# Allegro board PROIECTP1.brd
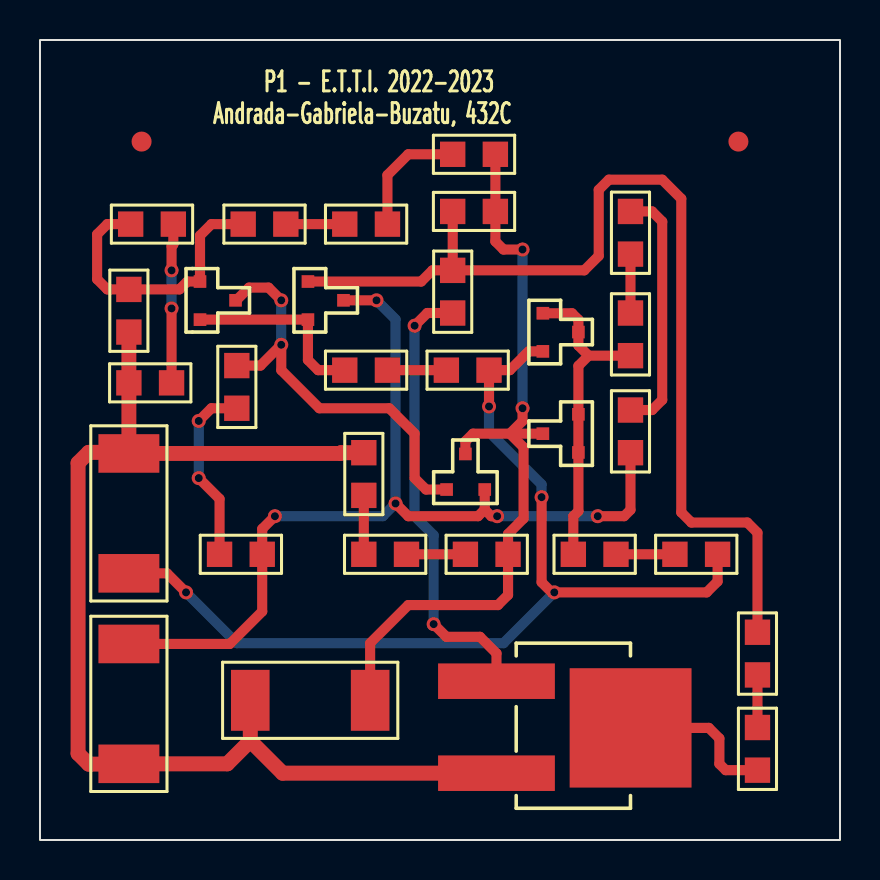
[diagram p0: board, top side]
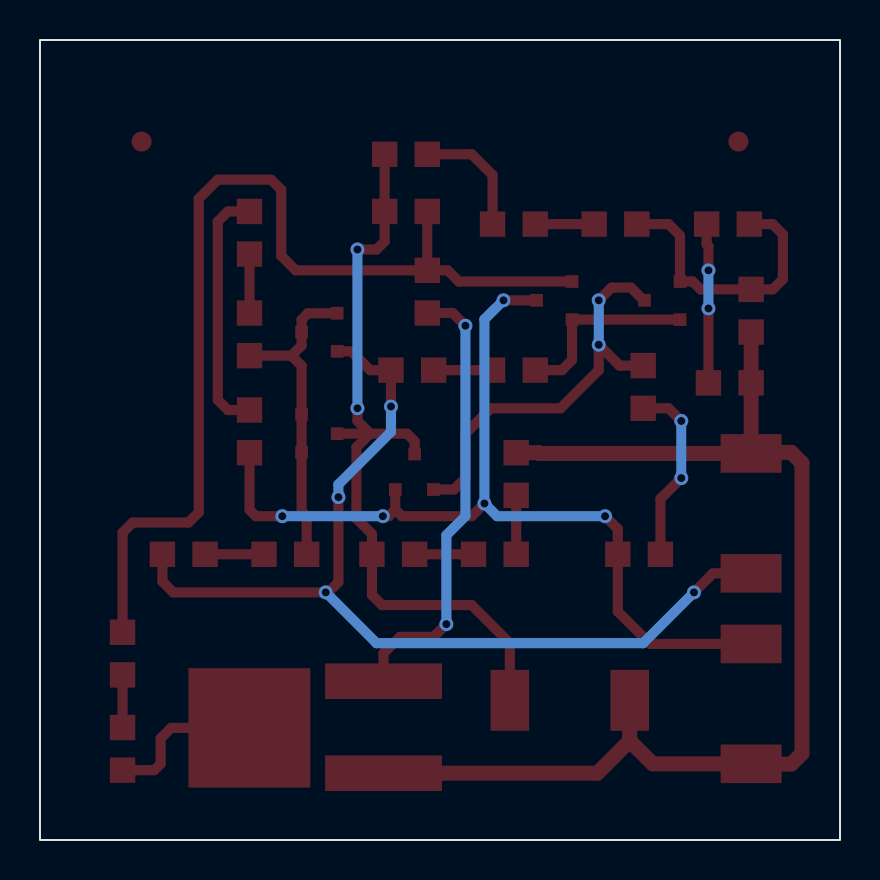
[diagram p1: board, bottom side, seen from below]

Outline 40.01 x 40.01 mm; copper layers: TOP, BOTTOM. Coordinates in mm from the lower left corner of the outline.
Outline path: rectangle 0,0 40.01,40.01

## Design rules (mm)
nets with their own width: min track width 0.508; nets N07562 N07566 N07674 N07678 N07682 N07786 N07830 N07834 N07854 N07900 N08156 N08192 N08330 N08354 N077021 N077181 N078461 N079281 N079441 N080220 N082081
nets with their own width: min track width 0.749; nets GND

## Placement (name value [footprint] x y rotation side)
C1  1n  [SMC0805]  4.45 25.4 90 top
C2  1n  [SMC0805]  20.64 34.29 0 top
J1  CON2  [SMR2512]  4.45 13.34 90 top
J2  CON2  [SMR2512]  4.45 3.81 90 top
J3  CON2  [SMR2512]  16.51 6.99 180 top
NOREF  Value  [unnamed]  34.92 34.92 0 top
NOREF#2  Value  [unnamed]  5.08 34.92 0 top
NOREF#3  -  [#2]  0 40.01 0 top
NOREF#4  -  [#2]  0 0 90 top
Q1  BC856B  [SOT23]  14.29 26.99 0 top
Q2  BC856B  [SOT23]  8.89 26.99 0 top
Q3  BC856B  [SOT23]  26.04 25.4 0 top
Q4  BC856B  [SOT23]  26.04 20.32 180 top
Q5  BC846B  [SOT23]  21.27 18.41 90 top
Q7  IRFR120  [TO252AA]  22.86 7.94 270 top
R1  8.2k  [SMR0805]  4.45 22.86 0 top
R2  220  [SMR0805]  6.67 30.8 180 top
R3  8.2k  [SMR0805]  10.16 30.8 0 top
R4  220  [SMR0805]  15.24 30.8 0 top
R5  910  [SMR0805]  21.27 14.29 0 top
R6  10  [SMR0805]  16.19 14.29 0 top
R7  33  [SMR0805]  16.19 19.37 270 top
R8  330  [SMR0805]  15.24 23.5 0 top
R9  68  [SMR0805]  20.32 23.5 0 top
R10  150  [SMR0805]  9.84 21.59 90 top
R11  10  [SMR0805]  11.11 14.29 180 top
R12  220  [SMR0805]  29.53 26.35 270 top
R13  68  [SMR0805]  29.53 31.43 270 top
R14  4.7  [SMR0805]  29.53 19.37 90 top
R15  150  [SMR0805]  26.67 14.29 0 top
R16  150  [SMR0805]  31.75 14.29 0 top
R17  10k  [SMR0805]  20.64 31.43 0 top
R18  100k  [SMR0805]  20.64 26.35 90 top
R19  15k  [SMR0805]  35.88 8.26 90 top
R20  510  [SMR0805]  35.88 3.49 90 top

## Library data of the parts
C1 C2 = C
J1-J3 = CON2
Q1-Q4 = BC856B
Q5 = BC846B
Q7 = IRFR120
R1-R20 = R

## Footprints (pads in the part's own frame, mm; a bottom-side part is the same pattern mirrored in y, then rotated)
SMC0805
  rect 1.27x1.27 smd: 1(0,0) 2(2.134,0)
SMR0805
  rect 1.27x1.27 smd: 1(0,0) 2(2.134,0)
SMR2512
  rect 1.93x3.048 smd: 1(0,0) 2(5.994,0)
SOT23
  rect 0.635x0.635 smd: 1(-0.889,0.94) 2(-0.889,-0.965) 3(0.889,0)
TO252AA
  rect 1.778x5.842 smd: 1(-0.004,-0.034) 3(4.596,-0.034)
  rect 5.969x6.096 smd: 2(2.332,6.673)
unnamed
  round 1 smd: 1(0,0)

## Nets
GND: C1.1 J1.2 J2.1 J3.2 Q7.3(S) R1.1 R7.1
N07562: R1.2 R2.1
N07566: C1.2 Q2.1(B) R2.2 R3.1
N07674: R3.2 R4.1
N07678: C2.1 R4.2
N07682: C2.2 J3.1 Q4.3(C) Q5.3(C) R5.2 R17.2
N07786: Q1.2(E) Q2.2(E) R8.1
N07830: J1.1 Q3.2(E) R9.2 R16.2
N07834: Q2.3(C) Q5.1(B) R10.2
N07854: J2.2 Q1.3(C) Q5.2(E) R11.1 R14.1
N07900: Q3.1(B) Q3.3(C) Q4.1(B) Q4.2(E) R12.2 R15.1
N08156: Q1.1(B) R17.1 R18.2 R19.2
N08192: Q7.1(G) R18.1
N08330: R8.2 R9.1
N08354: R19.1 R20.2
N077021: R5.1 R6.2
N077181: R6.1 R7.2
N078461: R10.1 R11.2
N079281: R12.1 R13.2
N079441: R13.1 R14.2
N080220: R15.2 R16.1
N082081: Q7.2(D) R20.1

Pads without a net: NOREF 1; NOREF#2 1

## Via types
v1: diameter 0.7, hole 0.4, TOP to BOTTOM, 19 vias

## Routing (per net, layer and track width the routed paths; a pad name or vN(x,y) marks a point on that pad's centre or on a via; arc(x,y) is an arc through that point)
GND: length 59.5
  TOP w0.749: 10.52,6.99 10.52,4.96 ; 10.52,4.96 12.13,3.34 Q7.3 ; 10.52,4.96 9.37,3.81 J2.1 4.43,3.79 2.44,3.79 1.91,4.32 1.91,18.85 2.44,19.38 4.39,19.38 J1.2 ; R7.1 15.06,19.37 15.02,19.33 J1.2 ; J1.2 R1.1 C1.1
N07562: length 8
  TOP w0.508: R2.1 6.67,29.78 6.58,29.69 v1(6.58,28.49) ; R1.2 v1(6.58,26.58)
  BOTTOM w0.508: v1(6.58,26.58) v1(6.58,28.49)
N07566: length 14.3
  TOP w0.508: R2.2 3.37,30.8 2.86,30.29 2.86,28.04 3.37,27.53 C1.2 6.97,27.53 7.37,27.93 8,27.93 8,30.23 8.57,30.8 R3.1
N07674: length 2.9
  TOP w0.508: R3.2 R4.1
N07678: length 6.1
  TOP w0.508: C2.1 18.41,34.29 17.37,33.25 R4.2
N07682: length 39.4
  TOP w0.508: 23.5,20.32 24.13,20.95 v1(24.13,21.59) ; 23.5,20.32 24.18,19.63 24.18,16.08 23.41,15.3 R5.2 23.41,12.26 22.9,11.75 18.41,11.75 16.51,9.84 J3.1 ; 23.5,20.32 21.65,20.32 21.27,19.94 Q5.3 ; 23.5,20.32 Q4.3 ; C2.2 R17.2 22.77,29.93 23.18,29.53 v1(24.13,29.53)
  BOTTOM w0.508: v1(24.13,29.53) v1(24.13,21.59)
N07786: length 9.5
  TOP w0.508: R8.1 13.91,23.5 13.4,24 Q1.2 8,26.02
N07830: length 49.1
  TOP w0.508: R16.2 33.88,12.93 33.34,12.38 v1(25.72,12.38) 25.59,12.38 25.08,12.89 v1(25.08,17.14) ; Q3.2 24.43,24.43 23.5,23.5 R9.2 v1(22.45,21.68) ; v1(7.3,12.38) 6.35,13.34 J1.1
  BOTTOM w0.508: v1(22.45,21.68) 22.45,20.41 25.08,17.78 v1(25.08,17.14) ; v1(25.72,12.38) 23.18,9.84 9.84,9.84 v1(7.3,12.38)
N07834: length 21
  TOP w0.508: v1(12.06,26.99) 11.43,27.62 10.45,27.62 9.82,26.99 Q2.3 ; Q5.1 19.3,17.53 18.73,18.1 18.73,20.32 17.46,21.59 13.97,21.59 12.06,23.5 v1(12.06,24.77) 11.02,23.72 R10.2
  BOTTOM w0.508: v1(12.06,24.77) v1(12.06,26.99)
N07854: length 47.1
  TOP w0.508: v1(27.89,16.19) 29.21,16.19 29.53,16.51 R14.1 ; Q1.3 v1(16.83,26.99) ; v1(22.86,16.19) 22.57,16.19 22.24,16.52 ; v1(17.78,16.83) 18.41,16.19 21.91,16.19 22.24,16.52 ; 22.24,16.52 Q5.2 ; J2.2 9.49,9.8 11.11,11.43 R11.1 11.11,15.56 v1(11.75,16.19)
  BOTTOM w0.508: v1(11.75,16.19) 17.14,16.19 v1(17.78,16.83) 17.78,26.04 v1(16.83,26.99) ; v1(27.89,16.19) v1(22.86,16.19)
N07900: length 16.3
  TOP w0.508: Q3.1 26.6,26.34 26.92,26.02 Q3.3 26.92,24.73 27.43,24.22 ; 27.43,24.22 R12.2 ; 27.43,24.22 26.92,23.71 Q4.2 Q4.1 26.92,16.45 26.67,16.19 R15.1
N08156: length 50.9
  TOP w0.508: R19.2 35.88,15.37 35.37,15.88 32.58,15.88 32.07,16.38 32.07,32.07 31.11,33.02 28.45,33.02 27.94,32.51 27.94,29.21 27.22,28.49 R18.2 ; R18.2 19.62,28.49 19.06,27.93 Q1.1 ; R18.2 R17.1
N08192: length 22.6
  TOP w0.508: Q7.1 22.83,9.33 22,10.16 20.32,10.16 v1(19.68,10.79) ; v1(18.73,25.72) 19.37,26.35 R18.1
  BOTTOM w0.508: v1(18.73,25.72) 18.73,16.19 19.68,15.24 v1(19.68,10.79)
N08330: length 2.9
  TOP w0.508: R8.2 R9.1
N08354: length 2.6
  TOP w0.508: R19.1 R20.2
N077021: length 2.9
  TOP w0.508: R6.2 R5.1
N077181: length 2.9
  TOP w0.508: R7.2 R6.1
N078461: length 9.3
  TOP w0.508: R10.1 8.57,21.59 v1(7.94,20.95) ; R11.2 8.98,17.06 v1(7.94,18.1)
  BOTTOM w0.508: v1(7.94,20.95) v1(7.94,18.1)
N079281: length 2.9
  TOP w0.508: R12.1 R13.2
N079441: length 12.5
  TOP w0.508: R14.2 30.61,21.5 31.11,22.01 31.11,30.92 30.61,31.43 R13.1
N080220: length 2.9
  TOP w0.508: R16.1 R15.2
N082081: length 8
  TOP w0.508: Q7.2 33.45,5.61 33.97,5.08 33.97,3.81 34.29,3.49 R20.1

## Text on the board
Ref Des/Silkscreen Top: Andrada-Gabriela-Buzatu, 432C | P1 - E.T.T.I. 2022-2023
XSECTION_CHART: *  SURFACE - AIR 0 MIL | L1: TOP CONDUCTOR - COPPER 0.8 MIL | *  DIELECTRIC - FR-4 59 MIL | L2: BOTTOM CONDUCTOR - COPPER 0.8 MIL | DESIGN CROSS SECTION CHART | ___________________________ | TOTAL THICKNESS 60.6 MIL | 1-2 | FIGURE | SIZE | 15.75 | DRILL CHART: TOP to BOTTOM | ALL UNITS ARE IN MILS | PLATED | QTY | 22
